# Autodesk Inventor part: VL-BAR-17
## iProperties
Created: 2005-08
Part Number: VL-BAR-17
Document SubType Name: Sheet Metal
Density: 1 g/cm^3
Mass: 2.87425 g
Surface Area: 55.6033 cm^2
Volume: 2.87425 cm^3
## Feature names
1. Rectangular Pattern1
2. Plate1
